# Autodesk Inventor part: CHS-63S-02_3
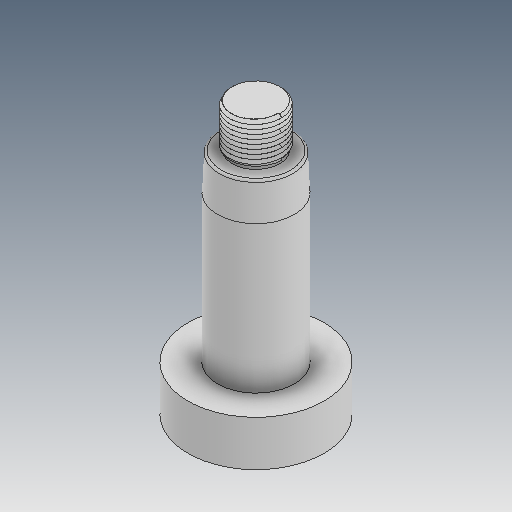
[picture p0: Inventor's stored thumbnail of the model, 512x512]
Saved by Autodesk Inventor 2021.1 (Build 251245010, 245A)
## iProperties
Created: 2019-05
Part Number: CHS-63S-02_3
Material: Ogólny
Document SubType Name: Modeling
Designer: user
Density: 1 g/cm^3
Appearance: Domyślna
Author: user
Revision Number: ÈÎºÎ
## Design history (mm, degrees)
feature "ÊäÈë1"
feature "ÊäÈë2"
node "Bryła1"
node "Bryła2"
